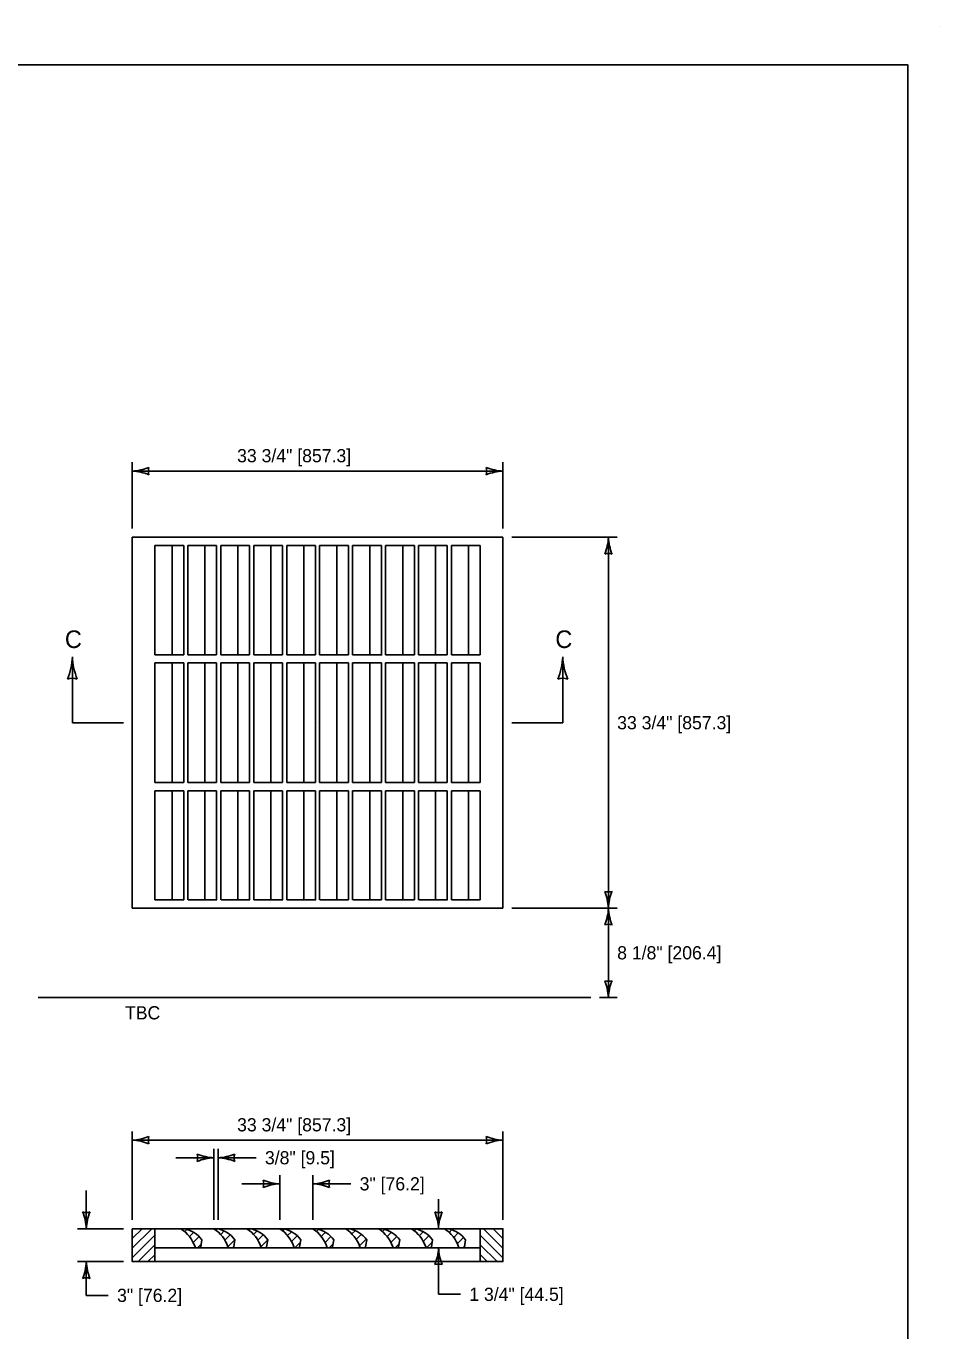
# Model space of a CAD drawing. Extents: x 49991.4 to 50041.6, y 49987.6 to 50011.4.
# Drawn here: x 50012.74 to 50016.9, y 49993.24 to 49999.18 of the extents above; entities that cross this region are included whole.
import ezdxf

# ---------------------------------------------------------------- set-up
doc = ezdxf.new("R2010")
doc.units = 0
for name, color, linetype in [('Level 1', 7, 'Continuous'), ('Level 2', 7, 'Continuous'), ('Level 3', 7, 'Continuous'), ('Level 6', 7, 'Continuous')]:
    doc.layers.add(name, color=color, linetype=linetype)

msp = doc.modelspace()

# ---------------------------------------------------------------- linework, layer by layer
at = {"layer": 'Level 1'}
for p, q in [((50016.9001, 49999.1756), (50016.9001, 49999.1756)), ((50013.2189, 49996.8492), (50014.9064, 49996.8492)), ((50013.2189, 49995.1617), (50013.2189, 49996.8492)), ((50014.9064, 49996.8492), (50014.9064, 49995.1617)), ((50013.322, 49996.8117), (50013.4533, 49996.8117)), ((50013.322, 49996.3149), (50013.322, 49996.8117)), ((50013.4002, 49996.3149), (50013.4002, 49996.8117)), ((50013.4533, 49996.3149), (50013.4533, 49996.8117)), ((50013.472, 49996.3149), (50013.472, 49996.8117)), ((50013.472, 49996.8117), (50013.6033, 49996.8117)), ((50013.5502, 49996.3149), (50013.5502, 49996.8117)), ((50013.6033, 49996.3149), (50013.6033, 49996.8117)), ((50013.622, 49996.3149), (50013.622, 49996.8117)), ((50013.622, 49996.8117), (50013.7533, 49996.8117)), ((50013.7002, 49996.3149), (50013.7002, 49996.8117)), ((50013.7533, 49996.3149), (50013.7533, 49996.8117)), ((50013.772, 49996.3149), (50013.772, 49996.8117)), ((50013.772, 49996.8117), (50013.9033, 49996.8117)), ((50013.8502, 49996.3149), (50013.8502, 49996.8117)), ((50013.9033, 49996.3149), (50013.9033, 49996.8117)), ((50013.922, 49996.3149), (50013.922, 49996.8117)), ((50013.922, 49996.8117), (50014.0533, 49996.8117)), ((50014.0002, 49996.3149), (50014.0002, 49996.8117)), ((50014.0533, 49996.3149), (50014.0533, 49996.8117)), ((50014.072, 49996.3149), (50014.072, 49996.8117)), ((50014.072, 49996.8117), (50014.2033, 49996.8117)), ((50014.1502, 49996.3149), (50014.1502, 49996.8117)), ((50014.2033, 49996.3149), (50014.2033, 49996.8117)), ((50014.222, 49996.3149), (50014.222, 49996.8117)), ((50014.222, 49996.8117), (50014.3533, 49996.8117)), ((50014.3002, 49996.3149), (50014.3002, 49996.8117)), ((50014.3533, 49996.3149), (50014.3533, 49996.8117)), ((50014.372, 49996.3149), (50014.372, 49996.8117)), ((50014.372, 49996.8117), (50014.5033, 49996.8117)), ((50014.4502, 49996.3149), (50014.4502, 49996.8117)), ((50014.5033, 49996.3149), (50014.5033, 49996.8117)), ((50014.522, 49996.3149), (50014.522, 49996.8117)), ((50014.522, 49996.8117), (50014.6533, 49996.8117)), ((50014.6002, 49996.3149), (50014.6002, 49996.8117)), ((50014.6533, 49996.3149), (50014.6533, 49996.8117)), ((50014.672, 49996.3149), (50014.672, 49996.8117)), ((50014.672, 49996.8117), (50014.8033, 49996.8117)), ((50014.7502, 49996.3149), (50014.7502, 49996.8117)), ((50014.8033, 49996.3149), (50014.8033, 49996.8117)), ((50013.322, 49996.3149), (50013.4533, 49996.3149)), ((50013.472, 49996.3149), (50013.6033, 49996.3149)), ((50013.622, 49996.3149), (50013.7533, 49996.3149)), ((50013.772, 49996.3149), (50013.9033, 49996.3149)), ((50013.922, 49996.3149), (50014.0533, 49996.3149)), ((50014.072, 49996.3149), (50014.2033, 49996.3149)), ((50014.222, 49996.3149), (50014.3569, 49996.3149)), ((50014.372, 49996.3149), (50014.5033, 49996.3149)), ((50014.522, 49996.3149), (50014.6533, 49996.3149)), ((50014.672, 49996.3149), (50014.8033, 49996.3149)), ((50013.4533, 49996.2774), (50013.322, 49996.2774)), ((50013.322, 49995.7336), (50013.322, 49996.2774)), ((50013.4002, 49995.7336), (50013.4002, 49996.2774)), ((50013.4533, 49995.7336), (50013.4533, 49996.2774)), ((50013.472, 49995.7336), (50013.472, 49996.2774)), ((50013.6033, 49996.2774), (50013.472, 49996.2774)), ((50013.5502, 49995.7336), (50013.5502, 49996.2774)), ((50013.6033, 49995.7336), (50013.6033, 49996.2774)), ((50013.622, 49995.7336), (50013.622, 49996.2774)), ((50013.7533, 49996.2774), (50013.622, 49996.2774)), ((50013.7002, 49995.7336), (50013.7002, 49996.2774)), ((50013.7533, 49995.7336), (50013.7533, 49996.2774)), ((50013.772, 49995.7336), (50013.772, 49996.2774)), ((50013.9033, 49996.2774), (50013.772, 49996.2774)), ((50013.8502, 49995.7336), (50013.8502, 49996.2774)), ((50013.9033, 49995.7336), (50013.9033, 49996.2774)), ((50013.922, 49995.7336), (50013.922, 49996.2774)), ((50014.0533, 49996.2774), (50013.922, 49996.2774)), ((50014.0002, 49995.7336), (50014.0002, 49996.2774)), ((50014.0533, 49995.7336), (50014.0533, 49996.2774)), ((50014.072, 49995.7336), (50014.072, 49996.2774)), ((50014.2033, 49996.2774), (50014.072, 49996.2774)), ((50014.1502, 49995.7336), (50014.1502, 49996.2774)), ((50014.2033, 49995.7336), (50014.2033, 49996.2774)), ((50014.222, 49995.7336), (50014.222, 49996.2774)), ((50014.3533, 49996.2774), (50014.222, 49996.2774)), ((50014.3002, 49995.7336), (50014.3002, 49996.2774)), ((50014.3533, 49995.7336), (50014.3533, 49996.2774)), ((50014.372, 49995.7336), (50014.372, 49996.2774)), ((50014.5033, 49996.2774), (50014.372, 49996.2774)), ((50014.4502, 49995.7336), (50014.4502, 49996.2774)), ((50014.5033, 49995.7336), (50014.5033, 49996.2774)), ((50014.522, 49995.7336), (50014.522, 49996.2774)), ((50014.6533, 49996.2774), (50014.522, 49996.2774)), ((50014.6002, 49995.7336), (50014.6002, 49996.2774)), ((50014.6533, 49995.7336), (50014.6533, 49996.2774)), ((50014.8033, 49996.2774), (50014.672, 49996.2774)), ((50014.672, 49995.7336), (50014.672, 49996.2774)), ((50014.7502, 49995.7336), (50014.7502, 49996.2774)), ((50014.8033, 49995.7336), (50014.8033, 49996.2774)), ((50014.0627, 49996.0055), (50014.0627, 49996.0055)), ((50013.4533, 49995.7336), (50013.322, 49995.7336)), ((50013.6033, 49995.7336), (50013.472, 49995.7336)), ((50013.7533, 49995.7336), (50013.622, 49995.7336)), ((50013.9033, 49995.7336), (50013.772, 49995.7336)), ((50014.0533, 49995.7336), (50013.922, 49995.7336)), ((50014.2033, 49995.7336), (50014.072, 49995.7336)), ((50014.3533, 49995.7336), (50014.222, 49995.7336)), ((50014.5033, 49995.7336), (50014.372, 49995.7336)), ((50014.6533, 49995.7336), (50014.522, 49995.7336)), ((50014.8033, 49995.7336), (50014.672, 49995.7336)), ((50013.4533, 49995.6961), (50013.322, 49995.6961)), ((50013.322, 49995.1992), (50013.322, 49995.6961)), ((50013.4002, 49995.1992), (50013.4002, 49995.6961)), ((50013.4533, 49995.1992), (50013.4533, 49995.6961)), ((50013.472, 49995.1992), (50013.472, 49995.6961)), ((50013.6033, 49995.6961), (50013.472, 49995.6961)), ((50013.5502, 49995.1992), (50013.5502, 49995.6961)), ((50013.6033, 49995.1992), (50013.6033, 49995.6961)), ((50013.622, 49995.1992), (50013.622, 49995.6961)), ((50013.7533, 49995.6961), (50013.622, 49995.6961)), ((50013.7002, 49995.1992), (50013.7002, 49995.6961)), ((50013.7533, 49995.1992), (50013.7533, 49995.6961)), ((50013.772, 49995.1992), (50013.772, 49995.6961)), ((50013.9033, 49995.6961), (50013.772, 49995.6961)), ((50013.8502, 49995.1992), (50013.8502, 49995.6961)), ((50013.9033, 49995.1992), (50013.9033, 49995.6961)), ((50013.922, 49995.1992), (50013.922, 49995.6961)), ((50014.0533, 49995.6961), (50013.922, 49995.6961)), ((50014.0002, 49995.1992), (50014.0002, 49995.6961)), ((50014.0533, 49995.1992), (50014.0533, 49995.6961)), ((50014.072, 49995.1992), (50014.072, 49995.6961)), ((50014.2033, 49995.6961), (50014.072, 49995.6961)), ((50014.1502, 49995.1992), (50014.1502, 49995.6961)), ((50014.2033, 49995.1992), (50014.2033, 49995.6961)), ((50014.222, 49995.1992), (50014.222, 49995.6961)), ((50014.3533, 49995.6961), (50014.222, 49995.6961)), ((50014.3002, 49995.1992), (50014.3002, 49995.6961)), ((50014.3533, 49995.1992), (50014.3533, 49995.6961)), ((50014.372, 49995.1992), (50014.372, 49995.6961)), ((50014.5033, 49995.6961), (50014.372, 49995.6961)), ((50014.4502, 49995.1992), (50014.4502, 49995.6961)), ((50014.5033, 49995.1992), (50014.5033, 49995.6961)), ((50014.522, 49995.1992), (50014.522, 49995.6961)), ((50014.6533, 49995.6961), (50014.522, 49995.6961)), ((50014.6002, 49995.1992), (50014.6002, 49995.6961)), ((50014.6533, 49995.1992), (50014.6533, 49995.6961)), ((50014.8033, 49995.6961), (50014.672, 49995.6961)), ((50014.672, 49995.1992), (50014.672, 49995.6961)), ((50014.7502, 49995.1992), (50014.7502, 49995.6961)), ((50014.8033, 49995.1992), (50014.8033, 49995.6961)), ((50013.4545, 49995.1992), (50013.322, 49995.1992)), ((50013.6045, 49995.1992), (50013.4732, 49995.1992)), ((50013.7545, 49995.1992), (50013.6232, 49995.1992)), ((50013.9045, 49995.1992), (50013.7732, 49995.1992)), ((50014.0545, 49995.1992), (50013.9232, 49995.1992)), ((50014.2033, 49995.1992), (50014.0733, 49995.1992)), ((50014.3533, 49995.1992), (50014.2233, 49995.1992)), ((50014.5033, 49995.1992), (50014.372, 49995.1992)), ((50014.6534, 49995.1992), (50014.5233, 49995.1992)), ((50014.8033, 49995.1992), (50014.672, 49995.1992)), ((50014.9064, 49995.1617), (50013.2189, 49995.1617)), ((50012.7902, 49994.7555), (50015.3064, 49994.7555)), ((50013.2189, 49993.6141), (50013.3078, 49993.703)), ((50013.2189, 49993.6583), (50013.2636, 49993.703)), ((50013.2189, 49993.7025), (50013.2194, 49993.703)), ((50013.322, 49993.703), (50014.8033, 49993.703)), ((50013.4595, 49993.703), (50013.4408, 49993.703)), ((50013.4579, 49993.6899), (50013.4685, 49993.7004)), ((50013.4793, 49993.6671), (50013.4988, 49993.6866)), ((50013.6095, 49993.703), (50013.5908, 49993.703)), ((50013.5985, 49993.6975), (50013.6039, 49993.703)), ((50013.6216, 49993.6764), (50013.6378, 49993.6926)), ((50013.7595, 49993.703), (50013.7408, 49993.703)), ((50013.7485, 49993.6975), (50013.7539, 49993.703)), ((50013.7716, 49993.6764), (50013.7878, 49993.6926)), ((50013.9095, 49993.703), (50013.8908, 49993.703)), ((50013.9038, 49993.6934), (50013.9126, 49993.7022)), ((50013.926, 49993.6714), (50013.944, 49993.6894)), ((50014.0595, 49993.703), (50014.0408, 49993.703)), ((50014.0579, 49993.6899), (50014.0685, 49993.7004)), ((50014.0793, 49993.6671), (50014.0988, 49993.6866)), ((50014.2095, 49993.703), (50014.1908, 49993.703)), ((50014.1957, 49993.6995), (50014.1992, 49993.703)), ((50014.2193, 49993.6789), (50014.2346, 49993.6942)), ((50014.3595, 49993.703), (50014.3408, 49993.703)), ((50014.3579, 49993.6899), (50014.3685, 49993.7004)), ((50014.3793, 49993.6671), (50014.3988, 49993.6866)), ((50014.5095, 49993.703), (50014.4908, 49993.703)), ((50014.5038, 49993.6933), (50014.5126, 49993.7022)), ((50014.526, 49993.6713), (50014.544, 49993.6894)), ((50014.6595, 49993.703), (50014.6408, 49993.703)), ((50014.6617, 49993.6864), (50014.6739, 49993.6986)), ((50014.6825, 49993.663), (50014.7033, 49993.6837)), ((50014.8178, 49993.703), (50014.9064, 49993.6144)), ((50014.862, 49993.703), (50014.9064, 49993.6586)), ((50014.9062, 49993.703), (50014.9064, 49993.7028)), ((50013.2189, 49993.5699), (50013.322, 49993.6731)), ((50013.2461, 49993.553), (50013.322, 49993.6289)), ((50013.4965, 49993.6401), (50013.5237, 49993.6673)), ((50013.5161, 49993.6155), (50013.5328, 49993.6322)), ((50013.5308, 49993.6211), (50013.5365, 49993.653)), ((50013.6404, 49993.6511), (50013.6647, 49993.6753)), ((50013.6547, 49993.6212), (50013.6865, 49993.653)), ((50013.6808, 49993.6211), (50013.6865, 49993.653)), ((50013.7904, 49993.6511), (50013.8147, 49993.6753)), ((50013.8047, 49993.6212), (50013.8365, 49993.653)), ((50013.8308, 49993.6211), (50013.8365, 49993.653)), ((50013.9439, 49993.6451), (50013.9697, 49993.671)), ((50013.9588, 49993.6158), (50013.9844, 49993.6415)), ((50013.9808, 49993.6211), (50013.9865, 49993.653)), ((50014.0965, 49993.6401), (50014.1237, 49993.6673)), ((50014.1161, 49993.6155), (50014.1328, 49993.6322)), ((50014.1308, 49993.6211), (50014.1365, 49993.653)), ((50014.2386, 49993.654), (50014.262, 49993.6774)), ((50014.2534, 49993.6246), (50014.2844, 49993.6556)), ((50014.2808, 49993.6211), (50014.2865, 49993.653)), ((50014.3965, 49993.6401), (50014.4237, 49993.6673)), ((50014.4161, 49993.6155), (50014.4328, 49993.6322)), ((50014.4308, 49993.6211), (50014.4365, 49993.653)), ((50014.5439, 49993.6451), (50014.5698, 49993.6709)), ((50014.5589, 49993.6158), (50014.5844, 49993.6414)), ((50014.5808, 49993.6211), (50014.5865, 49993.653)), ((50014.6989, 49993.6352), (50014.7273, 49993.6636)), ((50014.7234, 49993.6155), (50014.7312, 49993.6232)), ((50014.7308, 49993.6211), (50014.7365, 49993.653)), ((50014.8033, 49993.6733), (50014.9064, 49993.5702)), ((50014.8033, 49993.6291), (50014.8795, 49993.553)), ((50013.2903, 49993.553), (50013.322, 49993.5847)), ((50014.8033, 49993.6155), (50013.322, 49993.6155)), ((50013.511, 49993.6155), (50013.5246, 49993.6155)), ((50013.661, 49993.6155), (50013.6746, 49993.6155)), ((50013.811, 49993.6155), (50013.8246, 49993.6155)), ((50013.961, 49993.6155), (50013.9746, 49993.6155)), ((50014.111, 49993.6155), (50014.1246, 49993.6155)), ((50014.261, 49993.6155), (50014.2746, 49993.6155)), ((50014.411, 49993.6155), (50014.4246, 49993.6155)), ((50014.561, 49993.6155), (50014.5746, 49993.6155)), ((50014.758, 49993.6155), (50014.5679, 49993.6155)), ((50014.711, 49993.6155), (50014.7246, 49993.6155)), ((50014.8033, 49993.5849), (50014.8353, 49993.553)), ((50014.9064, 49993.553), (50013.2189, 49993.553))]:
    msp.add_line(p, q, dxfattribs=at)
for points in [[(49999.3835, 49998.9992), (50016.7501, 49998.9992), (50016.7501, 49987.7988), (49999.3835, 49987.7988)], [(50013.2189, 49993.703), (50013.322, 49993.703), (50013.322, 49993.553), (50013.2189, 49993.553)], [(50014.8033, 49993.703), (50014.9064, 49993.703), (50014.9064, 49993.553), (50014.8033, 49993.553)]]:
    msp.add_lwpolyline(points, close=True, dxfattribs=at)
for centre, radius, start, end in [((50013.3485, 49993.565), 0.166, 19.72864, 56.22955), ((50013.4256, 49993.5665), 0.1406, 37.94292, 76.03204), ((50013.4985, 49993.565), 0.166, 19.72864, 56.22955), ((50013.5756, 49993.5665), 0.1406, 37.94292, 76.03204), ((50013.6485, 49993.565), 0.166, 19.72864, 56.22955), ((50013.7256, 49993.5665), 0.1406, 37.94292, 76.03204), ((50013.7985, 49993.565), 0.166, 19.72864, 56.22955), ((50013.8756, 49993.5665), 0.1406, 37.94292, 76.03204), ((50013.9485, 49993.565), 0.166, 19.72864, 56.22955), ((50014.0256, 49993.5665), 0.1406, 37.94292, 76.03204), ((50014.0985, 49993.565), 0.166, 19.72864, 56.22955), ((50014.1756, 49993.5665), 0.1406, 37.94292, 76.03204), ((50014.2485, 49993.565), 0.166, 19.72864, 56.22955), ((50014.3256, 49993.5665), 0.1406, 37.94292, 76.03204), ((50014.3985, 49993.565), 0.166, 19.72864, 56.22955), ((50014.4756, 49993.5665), 0.1406, 37.94292, 76.03204), ((50014.5485, 49993.565), 0.166, 19.72864, 56.22955), ((50014.6256, 49993.5665), 0.1406, 37.94292, 76.03204), ((50013.511, 49993.6217), 0.00625, 186.20349, 270), ((50013.5246, 49993.6217), 0.00625, 270, 354.28941), ((50013.661, 49993.6217), 0.00625, 186.20349, 270), ((50013.6746, 49993.6217), 0.00625, 270, 354.28941), ((50013.811, 49993.6217), 0.00625, 186.20349, 270), ((50013.8246, 49993.6217), 0.00625, 270, 354.28941), ((50013.961, 49993.6217), 0.00625, 186.20349, 270), ((50013.9746, 49993.6217), 0.00625, 270, 354.28941), ((50014.111, 49993.6217), 0.00625, 186.20349, 270), ((50014.1246, 49993.6217), 0.00625, 270, 354.28941), ((50014.261, 49993.6217), 0.00625, 186.20349, 270), ((50014.2746, 49993.6217), 0.00625, 270, 354.28941), ((50014.411, 49993.6217), 0.00625, 186.20349, 270), ((50014.4246, 49993.6217), 0.00625, 270, 354.28941), ((50014.561, 49993.6217), 0.00625, 186.20349, 270), ((50014.5746, 49993.6217), 0.00625, 270, 354.28941), ((50014.711, 49993.6217), 0.00625, 186.20349, 270), ((50014.7246, 49993.6217), 0.00625, 270, 354.28941)]:
    msp.add_arc(centre, radius, start, end, dxfattribs=at)
at = {"layer": 'Level 3'}
for p, q in [((50013.2189, 49996.8892), (50013.2189, 49997.1907)), ((50014.9064, 49996.8892), (50014.9064, 49997.1907)), ((50013.2189, 49997.1507), (50014.9064, 49997.1507)), ((50014.9464, 49996.8492), (50015.4264, 49996.8492)), ((50015.3864, 49995.1617), (50015.3864, 49996.8492)), ((50014.9464, 49995.1617), (50015.4264, 49995.1617)), ((50015.3864, 49995.1617), (50015.3864, 49994.7555)), ((50015.3464, 49994.7555), (50015.4264, 49994.7555)), ((50013.2189, 49993.743), (50013.2189, 49994.1459)), ((50013.2189, 49994.1059), (50014.9064, 49994.1059)), ((50014.9064, 49993.743), (50014.9064, 49994.1459)), ((50013.5908, 49993.743), (50013.5908, 49994.0659)), ((50013.6095, 49993.743), (50013.6095, 49994.0659)), ((50013.4174, 49994.0259), (50013.5908, 49994.0259)), ((50013.783, 49994.0259), (50013.6095, 49994.0259)), ((50013.8908, 49993.743), (50013.8908, 49993.9472)), ((50014.0408, 49993.743), (50014.0408, 49993.9472)), ((50013.01, 49993.8764), (50013.01, 49993.703)), ((50013.7174, 49993.9072), (50013.8908, 49993.9072)), ((50014.2142, 49993.9072), (50014.0408, 49993.9072)), ((50014.6132, 49993.8372), (50014.6132, 49993.703)), ((50013.1789, 49993.703), (50012.97, 49993.703)), ((50014.6132, 49993.4044), (50014.6132, 49993.6155)), ((50013.1789, 49993.553), (50012.97, 49993.553)), ((50013.01, 49993.3995), (50013.01, 49993.553)), ((50013.11, 49993.3995), (50013.01, 49993.3995)), ((50014.7132, 49993.4044), (50014.6132, 49993.4044))]:
    msp.add_line(p, q, dxfattribs=at)
for centre, radius, start, end in [((50013.2074, 49997.3834), 0.233, 272.82731, 292.07716), ((50013.2098, 49996.9285), 0.2223, 67.45601, 87.63952), ((50013.3471, 49997.1507), 0.0548, 162.13882, 197.86118), ((50014.9156, 49997.3728), 0.2223, 247.45601, 267.63952), ((50014.7782, 49997.1507), 0.0548, 342.13882, 17.86118), ((50014.9179, 49996.918), 0.233, 92.82731, 112.07716), ((50015.1643, 49996.8584), 0.2223, 337.45601, 357.63952), ((50015.6191, 49996.8607), 0.233, 182.82731, 202.07716), ((50015.3864, 49996.721), 0.0548, 72.13882, 107.86118), ((50015.3864, 49995.29), 0.0548, 252.13882, 287.86118), ((50015.1537, 49995.1503), 0.233, 2.82731, 22.07716), ((50015.6085, 49995.1526), 0.2223, 157.45601, 177.63952), ((50015.1643, 49995.1709), 0.2223, 337.45601, 357.63952), ((50015.6191, 49995.1732), 0.233, 182.82731, 202.07716), ((50015.3864, 49995.0335), 0.0548, 72.13882, 107.86118), ((50015.3864, 49994.8837), 0.0548, 252.13882, 287.86118), ((50015.1537, 49994.744), 0.233, 2.82731, 22.07716), ((50015.6085, 49994.7463), 0.2223, 157.45601, 177.63952), ((50013.2074, 49994.3386), 0.233, 272.82731, 292.07716), ((50013.2098, 49993.8837), 0.2223, 67.45601, 87.63952), ((50013.3471, 49994.1059), 0.0548, 162.13882, 197.86118), ((50014.9156, 49994.328), 0.2223, 247.45601, 267.63952), ((50014.7782, 49994.1059), 0.0548, 342.13882, 17.86118), ((50014.9179, 49993.8731), 0.233, 92.82731, 112.07716), ((50013.6, 49994.248), 0.2223, 247.45601, 267.63952), ((50013.4626, 49994.0259), 0.0548, 342.13882, 17.86118), ((50013.598, 49994.2586), 0.233, 272.82731, 292.07716), ((50013.7377, 49994.0259), 0.0548, 162.13882, 197.86118), ((50013.6023, 49993.7931), 0.233, 92.82731, 112.07716), ((50013.6004, 49993.8037), 0.2223, 67.45601, 87.63952), ((50013.9, 49994.1293), 0.2223, 247.45601, 267.63952), ((50013.7626, 49993.9072), 0.0548, 342.13882, 17.86118), ((50014.0293, 49994.1399), 0.233, 272.82731, 292.07716), ((50014.169, 49993.9072), 0.0548, 162.13882, 197.86118), ((50013.9023, 49993.6745), 0.233, 92.82731, 112.07716), ((50014.0316, 49993.6851), 0.2223, 67.45601, 87.63952), ((50013.01, 49993.8312), 0.0548, 252.13882, 287.86118), ((50012.7773, 49993.6915), 0.233, 2.82731, 22.07716), ((50013.2321, 49993.6938), 0.2223, 157.45601, 177.63952), ((50014.6132, 49993.8312), 0.0548, 252.13882, 287.86118), ((50014.3805, 49993.6915), 0.233, 2.82731, 22.07716), ((50014.8353, 49993.6938), 0.2223, 157.45601, 177.63952), ((50014.3911, 49993.6246), 0.2223, 337.45601, 357.63952), ((50014.8459, 49993.627), 0.233, 182.82731, 202.07716), ((50012.7879, 49993.5621), 0.2223, 337.45601, 357.63952), ((50013.2427, 49993.5645), 0.233, 182.82731, 202.07716), ((50014.6132, 49993.4872), 0.0548, 72.13882, 107.86118), ((50013.01, 49993.4247), 0.0548, 72.13882, 107.86118)]:
    msp.add_arc(centre, radius, start, end, dxfattribs=at)
at = {"layer": 'Level 6'}
for p, q in [((50012.9464, 49996.0055), (50012.9464, 49996.3055)), ((50015.1789, 49996.0055), (50015.1789, 49996.3055)), ((50013.1789, 49996.0055), (50012.9464, 49996.0055)), ((50014.9464, 49996.0055), (50015.1789, 49996.0055))]:
    msp.add_line(p, q, dxfattribs=at)
for centre, radius, start, end in [((50012.6502, 49996.3177), 0.2964, 337.45601, 357.63952), ((50013.2567, 49996.3208), 0.3107, 182.82731, 202.07716), ((50014.8827, 49996.3177), 0.2964, 337.45601, 357.63952), ((50015.4892, 49996.3208), 0.3107, 182.82731, 202.07716), ((50012.9464, 49996.1345), 0.073, 72.13882, 107.86118), ((50015.1789, 49996.1345), 0.073, 72.13882, 107.86118)]:
    msp.add_arc(centre, radius, start, end, dxfattribs=at)

# ---------------------------------------------------------------- texts
at = {"layer": 'Level 2'}
for s, height, p in [('33 3/4" [857.3]', 0.06, (50013.6963, 49997.1907)), ('C', 0.08, (50012.9124, 49996.3455)), ('C', 0.08, (50015.1449, 49996.3455)), ('33 3/4" [857.3]', 0.06, (50015.4264, 49995.9755)), ('8 1/8" [206.4]', 0.06, (50015.4264, 49994.9286)), ('TBC', 0.06, (50013.186, 49994.6555)), ('33 3/4" [857.3]', 0.06, (50013.6963, 49994.1459)), ('3/8" [9.5]', 0.06, (50013.823, 49993.9959)), ('3" [76.2]', 0.06, (50014.2542, 49993.8772)), ('3" [76.2]', 0.06, (50013.15, 49993.3697)), ('1 3/4" [44.5]', 0.06, (50014.7532, 49993.3744))]:
    msp.add_text(s, height=height, dxfattribs=at).set_placement(p)

doc.saveas('drawing.dxf')
